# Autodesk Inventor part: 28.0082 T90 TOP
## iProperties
Created: 2007-04
Part Number: 28.0082 T90 TOP
Document SubType Name: Modeling
Designer: Andy Moles
Material: Aluminum-6061
Density: 2.71 g/cm^3
Author: Andy Moles
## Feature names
1. Extrusion1
2. Chamfer1
3. Hole1
4. Extrusion2
5. Extrusion3
